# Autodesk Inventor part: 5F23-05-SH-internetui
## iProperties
Created: 2005-10
Part Number: 5F23-05-SH-internetui
Document SubType Name: Modeling
Designer: Darius
Author: Darius
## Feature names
1. Base1
